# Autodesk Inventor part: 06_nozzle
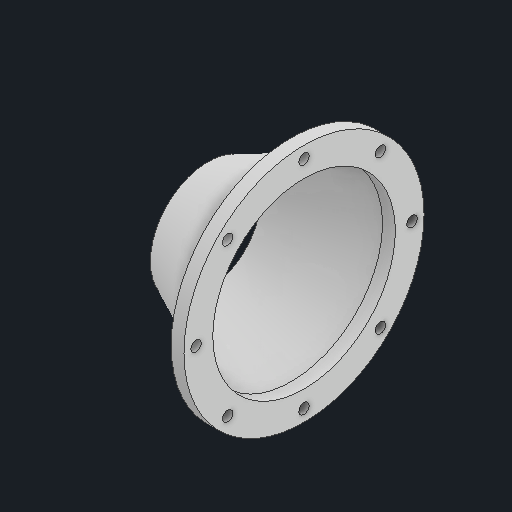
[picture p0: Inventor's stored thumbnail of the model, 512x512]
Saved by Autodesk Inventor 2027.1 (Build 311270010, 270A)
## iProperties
Created: 2026-10
Part Number: 06_nozzle
Material: Generic
Document SubType Name: Modeling
Designer: BHAVAN KUMAR
Density: 1 g/cm^3
Appearance: Default
Author: BHAVAN KUMAR
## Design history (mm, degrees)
sketch "Sketch1"
  geometry: L1 (0, 57)-(0, 75); L2 (0, 75)-(8, 75); L3 (8, 75)-(0, 57)
  constraints: 6 end point
sketch "Sketch2"
  geometry: L1 (0, 57)-(0, 75); L2 (0, 75)-(8, 75); L3 (8, 75)-(8, 60); L4 (8, 60)-(60, 36); L5 (60, 36)-(60, 33); L6 (60, 33)-(8, 57); L7 (8, 57)-(0, 57); L8 (0, 0)-(60, 0); L9 (72, 0)-(-12, 0) reference
  constraints: 16 end point
revolve "Nozzle_Body" sketch "Sketch2" stored, may be unused: angle "d0" = 0 deg
sketch "Sketch3"
  geometry: C1 r 3.25 at (67.5, 0)
  constraints: 1 centre point
extrude "Bolt_Hole" cut sketch "Sketch3" extent not by distance; stored distance "d1" = 0.13; taper "d2" = 0 deg
pattern_circular "Bolt_Pattern" dims angle "d4" = 360 deg
body "Solid1"
